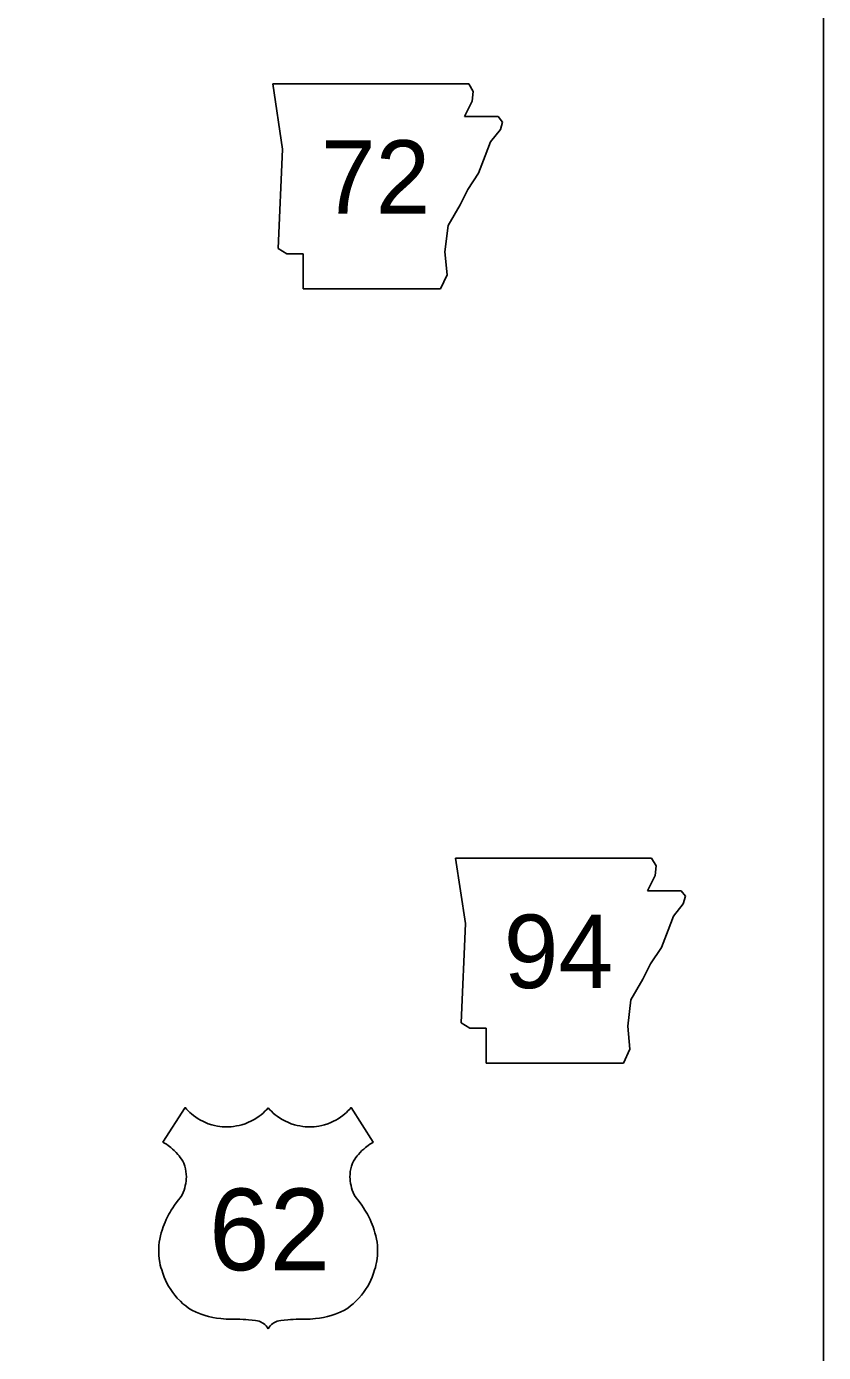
# Model space of a CAD drawing. Extents: x 6028647 to 6035072, y 5366486 to 5368495.
# Drawn here: x 6029195 to 6029287.9, y 5368116.1 to 5368270.4 of the extents above; entities that cross this region are included whole.
import ezdxf

# ---------------------------------------------------------------- set-up
doc = ezdxf.new("R2010")
doc.units = 0
for name, color, linetype in [('21', 7, 'Continuous'), ('22', 7, 'Continuous'), ('R_NoPlot', 7, 'Continuous')]:
    doc.layers.add(name, color=color, linetype=linetype)

msp = doc.modelspace()

# ---------------------------------------------------------------- linework, layer by layer
at = {"layer": '21'}
for p, q in [((6029223.73, 5368263.71), (6029224.87, 5368256.09)), ((6029247.07, 5368262.82), (6029246.55, 5368263.7)), ((6029246.95, 5368261.68), (6029247.07, 5368262.82)), ((6029246.06, 5368259.9), (6029246.95, 5368261.68)), ((6029249.99, 5368259.9), (6029246.06, 5368259.9)), ((6029250.5, 5368259.27), (6029249.99, 5368259.9)), ((6029250.24, 5368258.38), (6029250.5, 5368259.27)), ((6029249.1, 5368256.98), (6029250.24, 5368258.38)), ((6029224.87, 5368256.09), (6029224.36, 5368244.55)), ((6029248.47, 5368255.33), (6029249.1, 5368256.98)), ((6029247.71, 5368253.3), (6029248.47, 5368255.33)), ((6029246.44, 5368251.4), (6029247.71, 5368253.3)), ((6029245.55, 5368249.62), (6029246.44, 5368251.4)), ((6029244.15, 5368247.21), (6029245.55, 5368249.62)), ((6029243.77, 5368244.17), (6029244.15, 5368247.21)), ((6029224.36, 5368244.55), (6029225.38, 5368243.91)), ((6029225.38, 5368243.91), (6029227.28, 5368243.91)), ((6029227.28, 5368243.91), (6029227.28, 5368239.85)), ((6029244.03, 5368241.5), (6029243.77, 5368244.17)), ((6029243.27, 5368239.85), (6029244.03, 5368241.5)), ((6029227.28, 5368239.85), (6029243.27, 5368239.85)), ((6029245.03, 5368173.59), (6029246.17, 5368165.97)), ((6029268.37, 5368172.7), (6029267.85, 5368173.58)), ((6029268.25, 5368171.56), (6029268.37, 5368172.7)), ((6029267.36, 5368169.78), (6029268.25, 5368171.56)), ((6029271.29, 5368169.78), (6029267.36, 5368169.78)), ((6029271.8, 5368169.15), (6029271.29, 5368169.78)), ((6029270.4, 5368166.86), (6029271.54, 5368168.26)), ((6029271.54, 5368168.26), (6029271.8, 5368169.15)), ((6029269.77, 5368165.21), (6029270.4, 5368166.86)), ((6029246.17, 5368165.97), (6029245.66, 5368154.43)), ((6029269.01, 5368163.18), (6029269.77, 5368165.21)), ((6029267.74, 5368161.28), (6029269.01, 5368163.18)), ((6029266.85, 5368159.5), (6029267.74, 5368161.28)), ((6029265.45, 5368157.09), (6029266.85, 5368159.5)), ((6029265.07, 5368154.05), (6029265.45, 5368157.09)), ((6029245.66, 5368154.43), (6029246.68, 5368153.79)), ((6029246.68, 5368153.79), (6029248.58, 5368153.79)), ((6029248.58, 5368153.79), (6029248.58, 5368149.73)), ((6029265.33, 5368151.38), (6029265.07, 5368154.05)), ((6029264.57, 5368149.73), (6029265.33, 5368151.38)), ((6029248.58, 5368149.73), (6029264.57, 5368149.73))]:
    msp.add_line(p, q, dxfattribs=at)
for points in [[(6029223.73, 5368263.71), (6029246.55, 5368263.7)], [(6029245.03, 5368173.59), (6029267.85, 5368173.58)]]:
    msp.add_lwpolyline(points, dxfattribs=at)
at = {"layer": '22'}
for points in [[(6029223.19, 5368144.55), (6029222.99, 5368144.32), (6029222.8, 5368144.13), (6029222.59, 5368143.93), (6029222.36, 5368143.73), (6029222.13, 5368143.56), (6029221.86, 5368143.37), (6029221.57, 5368143.19), (6029221.24, 5368143.01), (6029220.82, 5368142.81), (6029220.5, 5368142.69), (6029220.14, 5368142.57), (6029219.8, 5368142.48), (6029219.49, 5368142.42), (6029219.17, 5368142.37), (6029218.87, 5368142.34), (6029218.46, 5368142.32), (6029218.13, 5368142.32), (6029217.84, 5368142.34), (6029217.57, 5368142.37), (6029217.29, 5368142.41), (6029216.94, 5368142.48), (6029216.62, 5368142.57), (6029216.22, 5368142.69), (6029215.89, 5368142.83), (6029215.58, 5368142.97), (6029215.31, 5368143.11), (6029215.05, 5368143.26), (6029214.76, 5368143.45), (6029214.5, 5368143.64), (6029214.27, 5368143.83), (6029214.08, 5368144), (6029213.88, 5368144.19), (6029213.69, 5368144.39), (6029213.54, 5368144.57), (6029210.94, 5368140.55), (6029211.13, 5368140.44), (6029211.35, 5368140.3), (6029211.56, 5368140.15), (6029211.84, 5368139.93), (6029212.06, 5368139.74), (6029212.26, 5368139.55), (6029212.46, 5368139.35), (6029212.66, 5368139.12), (6029212.81, 5368138.94), (6029212.96, 5368138.76), (6029213.1, 5368138.55), (6029213.25, 5368138.33), (6029213.38, 5368138.08), (6029213.48, 5368137.76), (6029213.56, 5368137.45), (6029213.62, 5368137.12), (6029213.65, 5368136.81), (6029213.66, 5368136.52), (6029213.65, 5368136.24), (6029213.63, 5368136.02), (6029213.59, 5368135.74), (6029213.54, 5368135.49), (6029213.47, 5368135.21), (6029213.39, 5368134.96), (6029213.29, 5368134.69), (6029213.12, 5368134.33), (6029212.95, 5368134.06), (6029212.74, 5368133.81), (6029212.48, 5368133.48), (6029212.28, 5368133.19), (6029212.08, 5368132.91), (6029211.91, 5368132.63), (6029211.76, 5368132.38), (6029211.63, 5368132.14), (6029211.48, 5368131.86), (6029211.32, 5368131.53), (6029211.18, 5368131.21), (6029211.09, 5368130.97), (6029210.97, 5368130.67), (6029210.85, 5368130.29), (6029210.74, 5368129.98), (6029210.65, 5368129.64), (6029210.56, 5368129.25), (6029210.51, 5368128.9), (6029210.46, 5368128.53), (6029210.44, 5368128.13), (6029210.44, 5368127.76), (6029210.46, 5368127.39), (6029210.5, 5368126.96), (6029210.57, 5368126.55), (6029210.63, 5368126.24), (6029210.7, 5368125.97), (6029210.79, 5368125.67), (6029210.91, 5368125.28), (6029211.08, 5368124.82), (6029211.23, 5368124.48), (6029211.4, 5368124.13), (6029211.59, 5368123.79), (6029211.84, 5368123.39), (6029212.09, 5368123.03), (6029212.33, 5368122.72), (6029212.61, 5368122.39), (6029212.97, 5368122.02), (6029213.27, 5368121.74), (6029213.59, 5368121.48)], [(6029223.19, 5368144.55), (6029223.39, 5368144.32), (6029223.58, 5368144.13), (6029223.79, 5368143.93), (6029224.02, 5368143.73), (6029224.25, 5368143.56), (6029224.52, 5368143.37), (6029224.81, 5368143.19), (6029225.14, 5368143.01), (6029225.56, 5368142.81), (6029225.88, 5368142.69), (6029226.24, 5368142.57), (6029226.58, 5368142.48), (6029226.89, 5368142.42), (6029227.21, 5368142.37), (6029227.51, 5368142.34), (6029227.92, 5368142.32), (6029228.25, 5368142.32), (6029228.54, 5368142.34), (6029228.81, 5368142.37), (6029229.09, 5368142.41), (6029229.44, 5368142.48), (6029229.76, 5368142.57), (6029230.16, 5368142.69), (6029230.49, 5368142.83), (6029230.8, 5368142.97), (6029231.07, 5368143.11), (6029231.33, 5368143.26), (6029231.62, 5368143.45), (6029231.88, 5368143.64), (6029232.11, 5368143.83), (6029232.3, 5368144), (6029232.49, 5368144.19), (6029232.69, 5368144.39), (6029232.84, 5368144.57), (6029235.44, 5368140.55), (6029235.25, 5368140.44), (6029235.03, 5368140.3), (6029234.82, 5368140.15), (6029234.54, 5368139.93), (6029234.32, 5368139.74), (6029234.12, 5368139.55), (6029233.92, 5368139.35), (6029233.72, 5368139.12), (6029233.57, 5368138.94), (6029233.42, 5368138.76), (6029233.27, 5368138.55), (6029233.13, 5368138.33), (6029233, 5368138.08), (6029232.9, 5368137.76), (6029232.82, 5368137.45), (6029232.76, 5368137.12), (6029232.73, 5368136.81), (6029232.72, 5368136.52), (6029232.73, 5368136.24), (6029232.75, 5368136.02), (6029232.78, 5368135.74), (6029232.84, 5368135.49), (6029232.91, 5368135.21), (6029232.99, 5368134.96), (6029233.09, 5368134.69), (6029233.26, 5368134.33), (6029233.43, 5368134.06), (6029233.64, 5368133.81), (6029233.9, 5368133.48), (6029234.1, 5368133.19), (6029234.3, 5368132.91), (6029234.47, 5368132.63), (6029234.62, 5368132.38), (6029234.75, 5368132.14), (6029234.9, 5368131.86), (6029235.06, 5368131.53), (6029235.2, 5368131.21), (6029235.29, 5368130.97), (6029235.41, 5368130.67), (6029235.53, 5368130.29), (6029235.63, 5368129.98), (6029235.73, 5368129.64), (6029235.82, 5368129.25), (6029235.87, 5368128.9), (6029235.92, 5368128.53), (6029235.94, 5368128.13), (6029235.94, 5368127.76), (6029235.92, 5368127.39), (6029235.88, 5368126.96), (6029235.81, 5368126.55), (6029235.75, 5368126.24), (6029235.68, 5368125.97), (6029235.59, 5368125.67), (6029235.47, 5368125.28), (6029235.3, 5368124.82), (6029235.15, 5368124.48), (6029234.98, 5368124.13), (6029234.79, 5368123.79), (6029234.54, 5368123.39), (6029234.29, 5368123.03), (6029234.05, 5368122.72), (6029233.77, 5368122.39), (6029233.41, 5368122.02), (6029233.11, 5368121.74), (6029232.79, 5368121.48)], [(6029213.59, 5368121.48), (6029213.91, 5368121.23), (6029214.3, 5368120.97), (6029214.8, 5368120.75), (6029215.37, 5368120.53), (6029215.84, 5368120.38), (6029216.26, 5368120.26), (6029216.74, 5368120.15), (6029217.19, 5368120.07), (6029217.67, 5368120), (6029218.28, 5368119.95), (6029218.74, 5368119.94), (6029219.14, 5368119.94), (6029219.52, 5368119.93), (6029219.91, 5368119.92), (6029220.28, 5368119.9), (6029220.6, 5368119.88), (6029220.91, 5368119.86), (6029221.32, 5368119.81), (6029221.71, 5368119.77), (6029221.95, 5368119.73), (6029222.14, 5368119.69), (6029222.38, 5368119.6), (6029222.51, 5368119.52), (6029222.63, 5368119.44), (6029222.79, 5368119.31), (6029222.95, 5368119.16), (6029223.08, 5368118.99), (6029223.19, 5368118.81)], [(6029232.79, 5368121.48), (6029232.47, 5368121.23), (6029232.08, 5368120.97), (6029231.58, 5368120.75), (6029231.01, 5368120.53), (6029230.54, 5368120.38), (6029230.12, 5368120.26), (6029229.64, 5368120.15), (6029229.19, 5368120.07), (6029228.71, 5368120), (6029228.1, 5368119.95), (6029227.64, 5368119.94), (6029227.24, 5368119.94), (6029226.86, 5368119.93), (6029226.47, 5368119.92), (6029226.1, 5368119.9), (6029225.78, 5368119.88), (6029225.47, 5368119.86), (6029225.06, 5368119.81), (6029224.67, 5368119.77), (6029224.43, 5368119.73), (6029224.24, 5368119.69), (6029224, 5368119.6), (6029223.87, 5368119.52), (6029223.75, 5368119.44), (6029223.59, 5368119.31), (6029223.43, 5368119.16), (6029223.3, 5368118.99), (6029223.19, 5368118.81)]]:
    msp.add_lwpolyline(points, dxfattribs=at)
at = {"layer": 'R_NoPlot'}
msp.add_lwpolyline([(6028702.18, 5368445.48), (6029287.88, 5368445.48), (6029287.88, 5367916.32), (6028702.18, 5367916.32)], close=True, dxfattribs=at)

# ---------------------------------------------------------------- texts
at = {"layer": '21'}
for s, p in [('72', (6029229.34, 5368248.59)), ('94', (6029250.64, 5368158.47))]:
    msp.add_text(s, height=8.554, dxfattribs=at).set_placement(p)
at = {"layer": '22'}
msp.add_text('62', height=9.504, dxfattribs=at).set_placement((6029216.29, 5368125.63))

doc.saveas('drawing.dxf')
